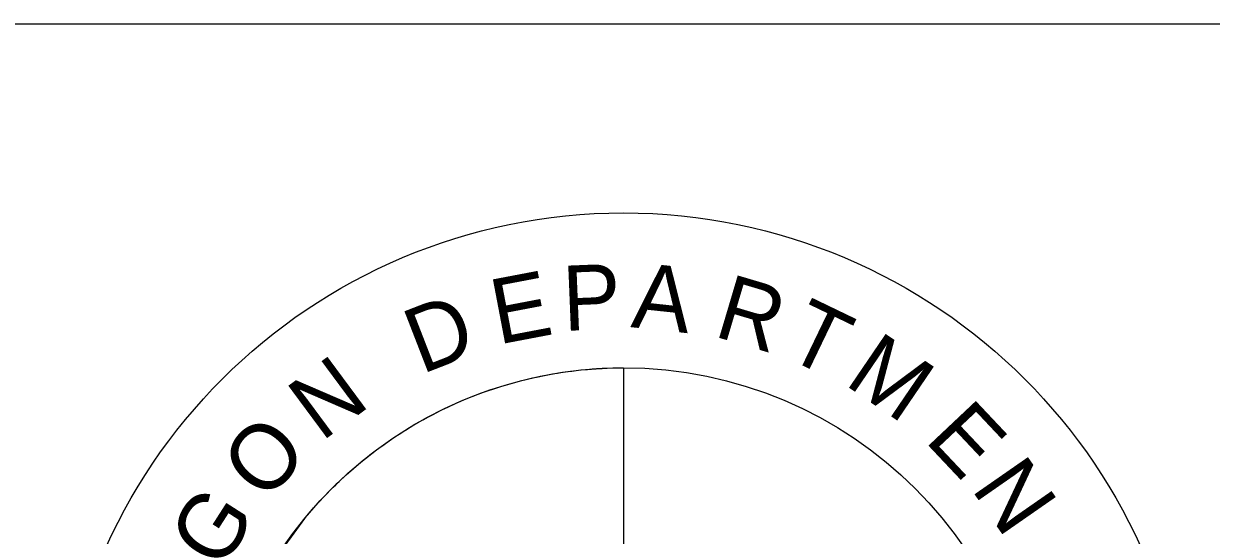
# Model space of a CAD drawing. Extents: x 0 to 1.42, y 0 to 0.92.
# Drawn here: x 1.3278 to 1.3801, y 0.115 to 0.1375 of the extents above; entities that cross this region are included whole.
import ezdxf

# ---------------------------------------------------------------- set-up
doc = ezdxf.new("R2010")
doc.units = 0
doc.layers.add('P_ODOT_PLAN_TBlock', color=7, linetype='Continuous')

msp = doc.modelspace()

# ---------------------------------------------------------------- linework, layer by layer
at = {"layer": 'P_ODOT_PLAN_TBlock'}
msp.add_line((1.3125, 0.1375), (1.395867, 0.1375), dxfattribs=at)
msp.add_lwpolyline([(1.338815, 0.113877), (1.340143, 0.115714), (1.34023, 0.115819), (1.340307, 0.115911), (1.340484, 0.116116), (1.340533, 0.116172), (1.340628, 0.116279), (1.340659, 0.116315), (1.34081, 0.116481), (1.340881, 0.116557), (1.340903, 0.116581), (1.341021, 0.116705), (1.34119, 0.11688), (1.34132, 0.117012), (1.341393, 0.117085), (1.341508, 0.117197), (1.341556, 0.117244), (1.341564, 0.117252), (1.341576, 0.117264), (1.341659, 0.117343), (1.341774, 0.11745), (1.341919, 0.117585), (1.342046, 0.1177), (1.342325, 0.117945), (1.342718, 0.118274), (1.342906, 0.118424), (1.343013, 0.118509), (1.343122, 0.118593), (1.343365, 0.118776), (1.343531, 0.118897), (1.343959, 0.119197), (1.344232, 0.11938), (1.344327, 0.119441), (1.344386, 0.11948), (1.344518, 0.119563), (1.344576, 0.119599), (1.344999, 0.119855), (1.345247, 0.119997), (1.345341, 0.12005), (1.345359, 0.12006), (1.34559, 0.120187), (1.345826, 0.12031), (1.345927, 0.120362), (1.346147, 0.120473), (1.346212, 0.120505), (1.346282, 0.120538), (1.346306, 0.12055), (1.346316, 0.120555), (1.34632, 0.120557), (1.346442, 0.120614), (1.346843, 0.120797), (1.34702, 0.120875), (1.347154, 0.120932), (1.347326, 0.121003), (1.34766, 0.121135), (1.347898, 0.121224), (1.348017, 0.121268), (1.348137, 0.12131), (1.348343, 0.121382), (1.34855, 0.121451), (1.34897, 0.121582), (1.349705, 0.121785), (1.350172, 0.121897), (1.35035, 0.121937), (1.350698, 0.122009), (1.35105, 0.122073), (1.351275, 0.122111), (1.3515, 0.122146), (1.351854, 0.122196), (1.351903, 0.122202), (1.352311, 0.122249), (1.352596, 0.122276), (1.352761, 0.12229), (1.352775, 0.122291), (1.352815, 0.122294), (1.352925, 0.122302), (1.352986, 0.122306), (1.353009, 0.122307), (1.353244, 0.122321), (1.353326, 0.122325), (1.353458, 0.122331), (1.353713, 0.12234), (1.353872, 0.122343), (1.354077, 0.122345), (1.35415, 0.122345), (1.354183, 0.122345), (1.354187, 0.112487)], dxfattribs=at)
for radius in [0.025, 0.018179]:
    msp.add_circle((1.354183, 0.104167), radius, dxfattribs=at)

# ---------------------------------------------------------------- texts
for s, rotation, p in [('E', 10.7909, (1.348659, 0.123362)), ('P', 2.3086, (1.351551, 0.123967)), ('A', 353.9045, (1.354473, 0.124139)), ('R', 343.4379, (1.358096, 0.123754)), ('D', 21.2107, (1.345278, 0.122046)), ('T', 334.276, (1.361165, 0.122881)), ('M', 325.7703, (1.363856, 0.121643)), ('N', 36.5188, (1.340874, 0.119061)), ('E', 313.3114, (1.367399, 0.119145)), ('O', 47.0792, (1.338369, 0.116369)), ('N', 304.8292, (1.369464, 0.117031)), ('G', 57.374, (1.336443, 0.113347))]:
    msp.add_text(s, height=0.002869, rotation=rotation, dxfattribs=at).set_placement(p)

doc.saveas('drawing.dxf')
